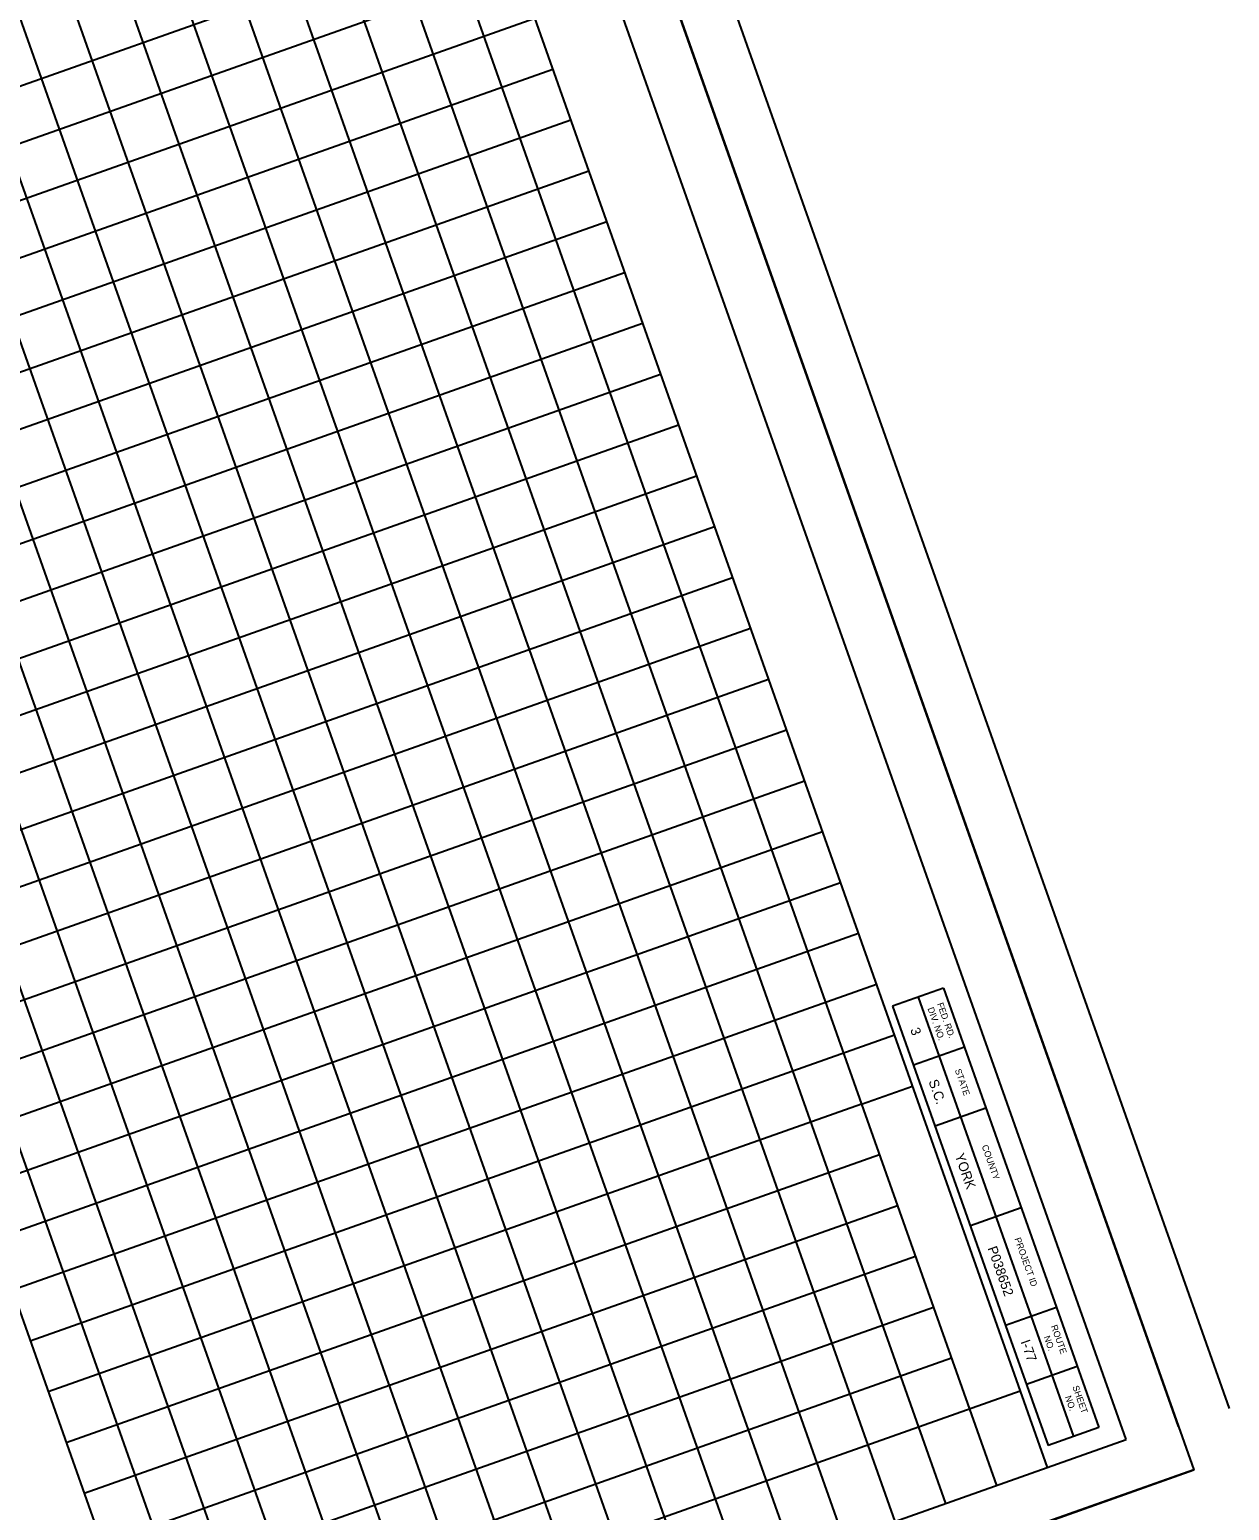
# Model space of a CAD drawing. Extents: x 2002686 to 2004357, y 1138437 to 1140501.
# Drawn here: x 2003801 to 2004357, y 1138785 to 1139472 of the extents above; entities that cross this region are included whole.
import ezdxf

# ---------------------------------------------------------------- set-up
doc = ezdxf.new("R2010")
doc.units = 0
for name, color, linetype in [('RD_SHT_Bndy', 7, 'Continuous'), ('RD_SHT_IplotShp', 7, 'Continuous'), ('RD_SHT_MjGrid', 7, 'Continuous'), ('RD_SHT_MnGrid', 7, 'Continuous'), ('RD_SHT_Snap', 7, 'Continuous'), ('RD_SHT_TX', 7, 'Continuous')]:
    doc.layers.add(name, color=color, linetype=linetype)

msp = doc.modelspace()

# ---------------------------------------------------------------- linework, layer by layer
at = {"layer": 'RD_SHT_Bndy'}
for p, q in [((2004357.14, 1138832.62), (2003770.16, 1140491.86)), ((2004333.57, 1138824.29), (2003746.59, 1140483.52)), ((2004309.2, 1138818.21), (2003750.57, 1140397.31)), ((2004224.57, 1139027.47), (2004201, 1139019.13)), ((2004224.57, 1139027.47), (2004276.93, 1138879.46)), ((2004201, 1139019.13), (2004253.36, 1138871.12)), ((2004212.78, 1139023.3), (2004265.15, 1138875.29)), ((2004234.24, 1139000.13), (2004210.67, 1138991.79)), ((2004244.25, 1138971.84), (2004220.68, 1138963.51)), ((2004260.59, 1138925.65), (2004237.02, 1138917.31)), ((2004276.93, 1138879.46), (2004253.36, 1138871.12)), ((2004265.15, 1138875.29), (2004284.82, 1138819.66)), ((2004276.93, 1138879.46), (2004296.61, 1138823.83)), ((2004253.36, 1138871.12), (2004273.04, 1138815.5)), ((2004286.6, 1138852.12), (2004263.03, 1138843.78)), ((2003319.32, 1138468.03), (2004309.2, 1138818.21)), ((2004296.61, 1138823.83), (2004273.04, 1138815.5))]:
    msp.add_line(p, q, dxfattribs=at)
at = {"layer": 'RD_SHT_IplotShp'}
msp.add_lwpolyline([(2003740.39, 1140501.06), (2004340.71, 1138804.11), (2003303.69, 1138437.25), (2002703.37, 1140134.19)], close=True, dxfattribs=at)
at = {"layer": 'RD_SHT_MjGrid'}
for p, q in [((2003714.04, 1140384.39), (2004272.67, 1138805.29)), ((2003313.37, 1140242.65), (2003872, 1138663.55)), ((2004035.05, 1139477), (2003634.38, 1139335.25)), ((2004076.73, 1139359.15), (2003676.07, 1139217.41)), ((2004118.42, 1139241.31), (2003717.76, 1139099.57)), ((2004160.11, 1139123.47), (2003759.44, 1138981.72)), ((2004201.8, 1139005.62), (2003801.13, 1138863.88)), ((2004186.57, 1138973.72), (2004210.14, 1138982.05)), ((2004219.92, 1138879.44), (2003842.82, 1138746.04)), ((2004260.17, 1138840.64), (2003859.5, 1138698.9))]:
    msp.add_line(p, q, dxfattribs=at)
msp.add_lwpolyline([(2004186.57, 1138973.72), (2004236.6, 1138832.3)], dxfattribs=at)
at = {"layer": 'RD_SHT_MnGrid'}
for p, q in [((2003690.47, 1140376.05), (2004186.57, 1138973.72)), ((2003666.9, 1140367.71), (2004225.53, 1138788.61)), ((2003643.34, 1140359.38), (2004201.97, 1138780.28)), ((2003619.77, 1140351.04), (2004178.4, 1138771.94)), ((2003596.2, 1140342.7), (2004154.83, 1138763.6)), ((2003572.63, 1140334.36), (2004131.26, 1138755.26)), ((2003549.06, 1140326.02), (2004107.69, 1138746.92)), ((2003525.49, 1140317.69), (2004084.12, 1138738.59)), ((2003501.92, 1140309.35), (2004060.55, 1138730.25)), ((2003478.35, 1140301.01), (2004036.99, 1138721.91)), ((2003454.79, 1140292.67), (2004013.42, 1138713.57)), ((2003431.22, 1140284.34), (2003989.85, 1138705.24)), ((2003407.65, 1140276), (2003966.28, 1138696.9)), ((2003384.08, 1140267.66), (2003942.71, 1138688.56)), ((2003360.51, 1140259.32), (2003919.14, 1138680.22)), ((2003336.94, 1140250.98), (2003895.57, 1138671.88)), ((2004018.37, 1139524.13), (2003617.7, 1139382.39)), ((2004026.71, 1139500.56), (2003626.04, 1139358.82)), ((2004043.38, 1139453.43), (2003642.72, 1139311.68)), ((2004051.72, 1139429.86), (2003651.05, 1139288.12)), ((2004060.06, 1139406.29), (2003659.39, 1139264.55)), ((2004068.4, 1139382.72), (2003667.73, 1139240.98)), ((2004085.07, 1139335.58), (2003684.4, 1139193.84)), ((2004093.41, 1139312.01), (2003692.74, 1139170.27)), ((2004101.75, 1139288.45), (2003701.08, 1139146.7)), ((2004110.09, 1139264.88), (2003709.42, 1139123.14)), ((2004126.76, 1139217.74), (2003726.09, 1139076)), ((2004135.1, 1139194.17), (2003734.43, 1139052.43)), ((2004143.44, 1139170.6), (2003742.77, 1139028.86)), ((2004151.77, 1139147.03), (2003751.11, 1139005.29)), ((2004168.45, 1139099.9), (2003767.78, 1138958.15)), ((2004176.79, 1139076.33), (2003776.12, 1138934.59)), ((2004185.13, 1139052.76), (2003784.46, 1138911.02)), ((2004193.46, 1139029.19), (2003792.8, 1138887.45)), ((2004186.57, 1138973.72), (2003809.47, 1138840.31)), ((2004194.91, 1138950.15), (2003817.81, 1138816.74)), ((2004203.25, 1138926.58), (2003826.15, 1138793.17)), ((2004211.58, 1138903.01), (2003834.48, 1138769.61)), ((2004228.26, 1138855.87), (2003851.16, 1138722.47)), ((2004236.6, 1138832.3), (2004249.1, 1138796.95))]:
    msp.add_line(p, q, dxfattribs=at)
at = {"layer": 'RD_SHT_Snap'}
msp.add_line((2003303.69, 1138437.25), (2004340.71, 1138804.11), dxfattribs=at)

# ---------------------------------------------------------------- texts
at = {"layer": 'RD_SHT_TX'}
for s, height, p in [('DIV. NO.', 3, (2004217.12, 1139018.04)), ('FED. RD.', 3, (2004221.49, 1139020.18)), ('3', 4.5, (2004209.08, 1139008.27)), ('STATE', 3, (2004229.79, 1138989.48)), ('S.C.', 4.5, (2004217.58, 1138984.26)), ('YORK', 4.5, (2004229.72, 1138949.95)), ('COUNTY', 3, (2004242.25, 1138954.25)), ('P038652', 4.5, (2004244.94, 1138906.92)), ('PROJECT ID', 3, (2004257.45, 1138911.28)), ('NO.', 3, (2004270.99, 1138865.76)), ('ROUTE', 3, (2004274.34, 1138870.78)), ('I-77', 4.5, (2004260.27, 1138863.58)), ('SHEET', 3, (2004284.3, 1138842.63)), ('NO.', 3, (2004280.83, 1138837.95))]:
    msp.add_text(s, height=height, rotation=289.48201, dxfattribs=at).set_placement(p)

doc.saveas('drawing.dxf')
